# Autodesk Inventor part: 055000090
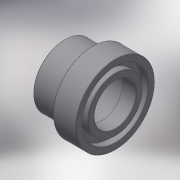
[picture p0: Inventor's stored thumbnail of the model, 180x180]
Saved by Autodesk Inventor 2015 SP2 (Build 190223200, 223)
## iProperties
Created: 2017-10
Part Number: 055000090
Material: Generic
Description: PLASSON FLANGE AD.+O-RING-CE 90
Document SubType Name: Modeling
Designer: KIM
Density: 1 g/cm^3
Appearance: Default
Author: KIM
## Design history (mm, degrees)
derived "055000.ipt"
feature "Solid1::055000.ipt"
tag "TaggingFeature1"
body "Solid1"
other parameters: "d0" = 61, "d1" = 105, "d3" = 81, "d4" = 16, "d5" = 51, "d6" = 125, "d8" = 4.8, "d11" = 0.9, "d12" = 4.8, "d15" = 6.6, "E_" = 105, "E_1" = 125, "l_" = 51, "B_" = 16, "H_" = 61, "d14" = 22
